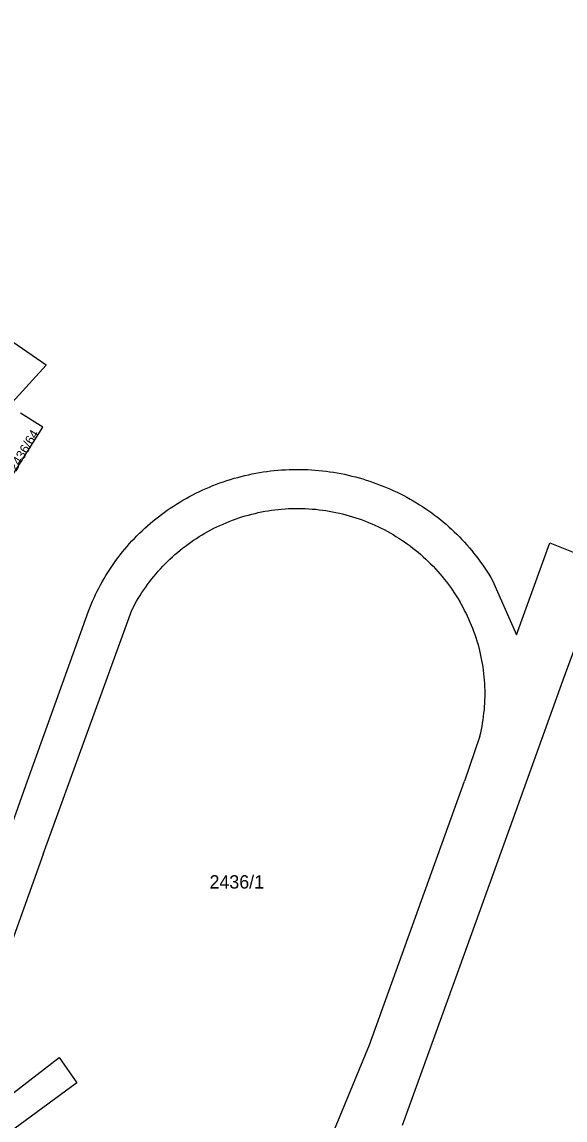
# Model space of a CAD drawing. Extents: x -869103 to -863415, y -1015889 to -1012477.
# Drawn here: x -865662.6 to -865593.3, y -1014844.8 to -1014704.6 of the extents above; entities that cross this region are included whole.
import ezdxf

# ---------------------------------------------------------------- set-up
doc = ezdxf.new("R2010")
doc.units = 0
for name, color, linetype in [('Hranice parcel', 7, 'Continuous'), ('Parcelní čísla', 7, 'Continuous'), ('Vnitřní kresba', 7, 'Continuous')]:
    doc.layers.add(name, color=color, linetype=linetype)

msp = doc.modelspace()

# ---------------------------------------------------------------- linework, layer by layer
at = {"layer": 'Hranice parcel'}
for points in [[(-865664.23, -1014753.64), (-865659.49, -1014748.41), (-865723.02, -1014704.59)], [(-865663.59, -1014762.22), (-865659.92, -1014756.33), (-865662.75, -1014754.56)]]:
    msp.add_lwpolyline(points, dxfattribs=at)
at = {"layer": 'Vnitřní kresba'}
for p, q in [((-865599.49, -1014782.86), (-865595.21, -1014771.11)), ((-865595.21, -1014771.11), (-865588.19, -1014773.9)), ((-865588.19, -1014773.9), (-865593.56, -1014788.65)), ((-865602.52, -1014775.91), (-865599.49, -1014782.86)), ((-865662.07, -1014802.07), (-865654.08, -1014779.82)), ((-865659.85, -1014810.85), (-865648.56, -1014779.69)), ((-865593.56, -1014788.65), (-865599.99, -1014806.51)), ((-865604.14, -1014795.78), (-865606.12, -1014801.55)), ((-865664.75, -1014809.68), (-865662.07, -1014802.07)), ((-865618.24, -1014835.19), (-865606.12, -1014801.55)), ((-865599.99, -1014806.51), (-865606.7, -1014825.17)), ((-865659.85, -1014810.85), (-865666.67, -1014829.8)), ((-865606.7, -1014825.17), (-865614.07, -1014845.5)), ((-865625.51, -1014852.77), (-865618.24, -1014835.19)), ((-865667.25, -1014844.11), (-865657.82, -1014836.81)), ((-865657.82, -1014836.81), (-865655.59, -1014840.04)), ((-865655.59, -1014840.04), (-865666, -1014847.69))]:
    msp.add_line(p, q, dxfattribs=at)
for points in [[(-865643.65, -1014766.68), (-865643.25, -1014766.42), (-865642.85, -1014766.16), (-865642.45, -1014765.91), (-865642.04, -1014765.67), (-865641.63, -1014765.43), (-865641.21, -1014765.2), (-865640.79, -1014764.98), (-865640.37, -1014764.77), (-865639.94, -1014764.56), (-865639.51, -1014764.35), (-865639.08, -1014764.16), (-865638.64, -1014763.97), (-865638.2, -1014763.79), (-865637.76, -1014763.62), (-865637.32, -1014763.45), (-865636.87, -1014763.3), (-865636.42, -1014763.14), (-865635.96, -1014763), (-865635.51, -1014762.86), (-865635.05, -1014762.74), (-865634.59, -1014762.61), (-865634.13, -1014762.5), (-865633.67, -1014762.4), (-865633.2, -1014762.3), (-865632.73, -1014762.21), (-865632.27, -1014762.12), (-865631.8, -1014762.05), (-865631.33, -1014761.98), (-865630.86, -1014761.92), (-865630.38, -1014761.87), (-865629.91, -1014761.82), (-865629.44, -1014761.79), (-865628.96, -1014761.76), (-865628.49, -1014761.74), (-865628.01, -1014761.72), (-865627.54, -1014761.72), (-865627.06, -1014761.72), (-865626.59, -1014761.73), (-865626.11, -1014761.75), (-865625.64, -1014761.77), (-865625.17, -1014761.81), (-865624.69, -1014761.85), (-865624.22, -1014761.9), (-865623.75, -1014761.95), (-865623.28, -1014762.02), (-865622.81, -1014762.09), (-865622.34, -1014762.17), (-865621.87, -1014762.26), (-865621.41, -1014762.35), (-865620.94, -1014762.46), (-865620.48, -1014762.57), (-865620.02, -1014762.69), (-865619.56, -1014762.81), (-865619.1, -1014762.94), (-865618.65, -1014763.08), (-865618.2, -1014763.23), (-865617.75, -1014763.39), (-865617.3, -1014763.55), (-865616.86, -1014763.72)], [(-865616.86, -1014763.72), (-865616.42, -1014763.89), (-865615.99, -1014764.07), (-865615.56, -1014764.25), (-865615.13, -1014764.44), (-865614.71, -1014764.64), (-865614.29, -1014764.85), (-865613.87, -1014765.06), (-865613.46, -1014765.28), (-865613.05, -1014765.51), (-865612.64, -1014765.74), (-865612.24, -1014765.98), (-865611.84, -1014766.23), (-865611.45, -1014766.48), (-865611.06, -1014766.74), (-865610.68, -1014767.01), (-865610.3, -1014767.28), (-865609.92, -1014767.56), (-865609.55, -1014767.84), (-865609.18, -1014768.13), (-865608.82, -1014768.43), (-865608.46, -1014768.73), (-865608.11, -1014769.04), (-865607.77, -1014769.36), (-865607.43, -1014769.68), (-865607.09, -1014770.01), (-865606.76, -1014770.34), (-865606.43, -1014770.67), (-865606.11, -1014771.02), (-865605.8, -1014771.36), (-865605.49, -1014771.72), (-865605.19, -1014772.08), (-865604.9, -1014772.44), (-865604.61, -1014772.81), (-865604.33, -1014773.18), (-865604.05, -1014773.56), (-865603.78, -1014773.94), (-865603.51, -1014774.32), (-865603.25, -1014774.71), (-865603, -1014775.11), (-865602.76, -1014775.51), (-865602.52, -1014775.91)], [(-865654.08, -1014779.82), (-865653.91, -1014779.39), (-865653.74, -1014778.96), (-865653.56, -1014778.54), (-865653.37, -1014778.12), (-865653.18, -1014777.7), (-865652.97, -1014777.29), (-865652.77, -1014776.88), (-865652.55, -1014776.47), (-865652.33, -1014776.07), (-865652.1, -1014775.67), (-865651.86, -1014775.27), (-865651.62, -1014774.88), (-865651.37, -1014774.49), (-865651.12, -1014774.11), (-865650.86, -1014773.73), (-865650.59, -1014773.35), (-865650.31, -1014772.98), (-865650.03, -1014772.62), (-865649.75, -1014772.26), (-865649.46, -1014771.9), (-865649.16, -1014771.55), (-865648.85, -1014771.2), (-865648.54, -1014770.86), (-865648.23, -1014770.53), (-865647.91, -1014770.2), (-865647.58, -1014769.87), (-865647.25, -1014769.55), (-865646.91, -1014769.24), (-865646.57, -1014768.93), (-865646.22, -1014768.63), (-865645.87, -1014768.33), (-865645.51, -1014768.04), (-865645.15, -1014767.76), (-865644.78, -1014767.48), (-865644.41, -1014767.21), (-865644.03, -1014766.94), (-865643.65, -1014766.68)], [(-865648.56, -1014779.69), (-865648.36, -1014779.31), (-865648.16, -1014778.93), (-865647.95, -1014778.56), (-865647.73, -1014778.19), (-865647.5, -1014777.82), (-865647.27, -1014777.46), (-865647.03, -1014777.1), (-865646.79, -1014776.75), (-865646.54, -1014776.4), (-865646.28, -1014776.06), (-865646.01, -1014775.71), (-865645.74, -1014775.38), (-865645.47, -1014775.05), (-865645.19, -1014774.73), (-865644.9, -1014774.41), (-865644.61, -1014774.09), (-865644.31, -1014773.78), (-865644, -1014773.48), (-865643.69, -1014773.18), (-865643.38, -1014772.89), (-865643.06, -1014772.6), (-865642.73, -1014772.32), (-865642.4, -1014772.05), (-865642.07, -1014771.78), (-865641.72, -1014771.52), (-865641.38, -1014771.26), (-865641.03, -1014771.01), (-865640.68, -1014770.77), (-865640.32, -1014770.53), (-865639.96, -1014770.3), (-865639.59, -1014770.07), (-865639.22, -1014769.86), (-865638.84, -1014769.65), (-865638.46, -1014769.44), (-865638.08, -1014769.24), (-865637.7, -1014769.05), (-865637.31, -1014768.87), (-865636.92, -1014768.7), (-865636.52, -1014768.53), (-865636.12, -1014768.36), (-865635.72, -1014768.21), (-865635.32, -1014768.06), (-865634.91, -1014767.92), (-865634.5, -1014767.79), (-865634.09, -1014767.67), (-865633.68, -1014767.55), (-865633.26, -1014767.44), (-865632.84, -1014767.34), (-865632.43, -1014767.24), (-865632, -1014767.15), (-865631.58, -1014767.07), (-865631.16, -1014767), (-865630.73, -1014766.94), (-865630.31, -1014766.88), (-865629.88, -1014766.83)], [(-865629.88, -1014766.83), (-865629.45, -1014766.79), (-865629.01, -1014766.76), (-865628.58, -1014766.73), (-865628.14, -1014766.72), (-865627.71, -1014766.71), (-865627.27, -1014766.71), (-865626.83, -1014766.71), (-865626.4, -1014766.73), (-865625.96, -1014766.75), (-865625.53, -1014766.78), (-865625.09, -1014766.82), (-865624.66, -1014766.87), (-865624.23, -1014766.92), (-865623.8, -1014766.98), (-865623.37, -1014767.05), (-865622.94, -1014767.13), (-865622.51, -1014767.22), (-865622.08, -1014767.31), (-865621.66, -1014767.41), (-865621.24, -1014767.52), (-865620.82, -1014767.64), (-865620.4, -1014767.76), (-865619.98, -1014767.89), (-865619.57, -1014768.03), (-865619.16, -1014768.18), (-865618.75, -1014768.33), (-865618.35, -1014768.49), (-865617.95, -1014768.66), (-865617.55, -1014768.84), (-865617.15, -1014769.02), (-865616.76, -1014769.21), (-865616.37, -1014769.41), (-865615.99, -1014769.62), (-865615.61, -1014769.83), (-865615.23, -1014770.05), (-865614.86, -1014770.27), (-865614.49, -1014770.5), (-865614.12, -1014770.74), (-865613.76, -1014770.99), (-865613.41, -1014771.24), (-865613.06, -1014771.5), (-865612.71, -1014771.76), (-865612.37, -1014772.03), (-865612.03, -1014772.31), (-865611.7, -1014772.59), (-865611.37, -1014772.88), (-865611.05, -1014773.18), (-865610.74, -1014773.48), (-865610.43, -1014773.78), (-865610.12, -1014774.09), (-865609.82, -1014774.41), (-865609.53, -1014774.74), (-865609.24, -1014775.06), (-865608.96, -1014775.4), (-865608.69, -1014775.73), (-865608.42, -1014776.08), (-865608.16, -1014776.43), (-865607.9, -1014776.78), (-865607.65, -1014777.14), (-865607.41, -1014777.5), (-865607.17, -1014777.86), (-865606.94, -1014778.23), (-865606.72, -1014778.61)], [(-865604.14, -1014795.78), (-865604.04, -1014795.37), (-865603.96, -1014794.95), (-865603.87, -1014794.54), (-865603.8, -1014794.12), (-865603.73, -1014793.7), (-865603.68, -1014793.28), (-865603.63, -1014792.86), (-865603.58, -1014792.44), (-865603.55, -1014792.02), (-865603.52, -1014791.59), (-865603.5, -1014791.17), (-865603.49, -1014790.74), (-865603.49, -1014790.32), (-865603.49, -1014789.9), (-865603.51, -1014789.47), (-865603.53, -1014789.05), (-865603.55, -1014788.63), (-865603.59, -1014788.2), (-865603.63, -1014787.78), (-865603.69, -1014787.36), (-865603.74, -1014786.94), (-865603.81, -1014786.52), (-865603.89, -1014786.11), (-865603.97, -1014785.69), (-865604.06, -1014785.28), (-865604.16, -1014784.86), (-865604.26, -1014784.45), (-865604.37, -1014784.04), (-865604.49, -1014783.64), (-865604.62, -1014783.23), (-865604.76, -1014782.83), (-865604.9, -1014782.43), (-865605.05, -1014782.04), (-865605.21, -1014781.64), (-865605.37, -1014781.25), (-865605.54, -1014780.86), (-865605.72, -1014780.48), (-865605.91, -1014780.1), (-865606.1, -1014779.72), (-865606.3, -1014779.35), (-865606.51, -1014778.98), (-865606.72, -1014778.61)]]:
    msp.add_lwpolyline(points, dxfattribs=at)

# ---------------------------------------------------------------- texts
at = {"layer": 'Parcelní čísla'}
msp.add_text('2436/64', height=1.19, rotation=59, dxfattribs=at).set_placement((-865663.32, -1014762.06))
msp.add_text('2436/1', height=1.7, dxfattribs=at).set_placement((-865638.64, -1014815.24))

doc.saveas('drawing.dxf')
